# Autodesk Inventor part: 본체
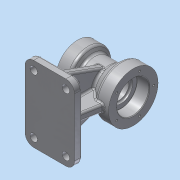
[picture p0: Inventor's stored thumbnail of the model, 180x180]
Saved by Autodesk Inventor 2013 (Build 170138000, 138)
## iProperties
Created: 2015-08
Part Number: 본체
Material: 알루미늄 6061
Document SubType Name: Modeling
Designer: WINDOWS7
Density: 2.71 g/cm^3
Mass: 1062.55 g
Surface Area: 748.24 cm^2
Volume: 392.085 cm^3
Author: WINDOWS7
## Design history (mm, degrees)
sketch "스케치1"
  geometry: L1 (-45, 0)-(45, 0); L2 (-45, 0)-(-45, 35); L3 (-45, 35)-(-25, 35); L4 (-25, 35)-(-19.804, 26); L5 (-19.804, 26)-(8.315, 26); L6 (8.315, 26)-(25, 40); L7 (25, 40)-(45, 40); L8 (45, 40)-(45, 0); 2 further points
  constraints: 16 end point, 3 parallel, 2 perpendicular, 1 coincident, 1 horizontal, 1 midpoint
  dimensions: "d0" = 90 distance of L1.start L1.end; "d2" = 80 diameter of L7 L1; "d3" = 70 diameter of L3 L1; "d4" = 20 distance of L2.end L3.end; "d5" = 20 distance of L6.end L7.end; "d6" = 60 deg angle of L5 L4; "d7" = 40 deg angle of L5 L6; "d8" = 52 diameter of L5 L1
revolve "회전1" sketch "스케치1" stored, may be unused: angle "d9" = 90 deg
node "작업 평면1"
sketch "스케치2"
  geometry: L1 (-40, 61)-(40, 61); L2 (40, 61)-(40, -61); L3 (40, -61)-(-40, -61); L4 (-40, -61)-(-40, 61); 3 further points
  constraints: 8 end point, 2 midpoint, 2 parallel, 1 horizontal, 1 horizontal alignment, 1 perpendicular, 1 vertical alignment
  dimensions: "d11" = 80 distance of L1.start L1.end; "d13" = 122 distance of L1.end L2.end
extrude "돌출1" join sketch "스케치2" distance "d14" = 12; taper "d15" = 0 deg
node "작업 평면2"
sketch "스케치3"
  geometry: L1 (-40, -90)-(40, -90) reference; L2 (-40, -90)-(-40, -78) reference; L3 (40, -78)-(-40, -78) reference; L4 (40, -90)-(40, -78) reference; L5 (30, -78)-(41.917, -10.416); L6 (41.917, -10.416)-(-30, -10.416); L7 (-30, -10.416)-(-30, -78); 1 further point
  constraints: 6 end point, 2 perpendicular, 2 point on line
  dimensions: "d17" = 10 distance of L3.start L5.start; "d18" = 80 deg angle of L3 L5; "d19" = 10 distance from line of L7 L2.end; "d20" = 71.91687 distance of L5.end L6.end
extrude "돌출2" join sketch "스케치3" stored distance "d21" = 12; taper "d22" = 0 deg
sketch "스케치4"
  geometry: L1 (-90, 61)-(-90, -61) reference; L2 (-90, 61)-(-78, 61) reference; L3 (-78, -61)-(-78, 61) reference; L4 (-90, -61)-(-78, -61) reference; L5 (-78, -51)-(7.172, -20); L6 (7.172, -20)-(7.172, 20); L7 (7.172, 20)-(-78, 51); 1 further point
  constraints: 6 end point, 2 point on line, 1 equal length, 1 perpendicular
  dimensions: "d23" = 10 distance of L3.start L5.start; "d24" = 70 deg angle of L3 L5; "d25" = 10 distance of L2.end L7.end; "d26" = 40 distance of L5.end L6.end
extrude "돌출3" join sketch "스케치4" stored distance "d27" = 12; taper "d28" = 0 deg
sketch "스케치5"
  geometry: L1 (40, 61)-(-40, 61) reference; L2 (40, -61)-(40, 61) reference; C1 r 6 at (26, 47); C2 r 6 at (26, -47); C3 r 6 at (-26, -47); C4 r 6 at (-26, 47); 1 further point
  constraints: 4 centre point, 3 equal radius, 2 horizontal alignment, 2 vertical alignment
  dimensions: "d29" = 12 diameter of C1; "d31" = 14 distance from line of L1 C1.centre; "d32" = 94 distance of C2.centre C1.centre; "d33" = 14 distance from line of L2 C2.centre; "d34" = 52 distance of C3.centre C2.centre
extrude "돌출4" cut sketch "스케치5" stored distance "d35" = 12; taper "d36" = 0 deg
sketch "스케치6"
  geometry: L1 (-90, 61)-(-90, -61) reference; L2 (-78, -61)-(-78, 61) reference; L3 (-54, 30)-(-60, 30); L4 (-54, 18)-(-60, 18); L5 (-54, -18)-(-60, -18); L6 (-54, -30)-(-60, -30); A1 r 6 centre (-60, 24) between (-60, 30) and (-60, 18); A2 r 6 centre (-54, 24) between (-54, 18) and (-54, 30); A3 r 6 centre (-60, -24) between (-60, -18) and (-60, -30); A4 r 6 centre (-54, -24) between (-54, -30) and (-54, -18); 3 further points
  constraints: 8 end point, 8 point on circle, 4 centre point, 4 tangent, 3 equal radius, 3 parallel, 2 horizontal alignment, 1 coincident, 1 midpoint, 1 perpendicular
  dimensions: "d41" = 24 vertical distance of point (-90, 0) point (-60, 24); "d42" = 12 diameter of A1; "d43" = 18 distance from line of A1.centre L2; "d44" = 18 dimension on A1 A2; "d45" = 18 dimension on A3 A4; "d46" = 18 distance from line of L2 A3.centre; "d47" = 48 distance of A3.centre point (-60, 24)
extrude "돌출5" cut sketch "스케치6" stored distance "d48" = 12; taper "d49" = 0 deg
fillet "모깎기1" dims "d50" = 14
sketch "스케치7"
  geometry: C1 r 40 at (0, 0) reference; C2 r 26 at (0, 0)
  constraints: 1 centre point, 1 coincident
  dimensions: "d51" = 52 diameter of C2
extrude "돌출6" cut sketch "스케치7" distance "d53" = 20; taper "d54" = 0 deg
sketch "스케치8"
  geometry: C1 r 26 at (0, 0) reference; C2 r 19 at (0, 0)
  constraints: 1 centre point, 1 coincident
  dimensions: "d55" = 38 diameter of C2
extrude "돌출7" cut sketch "스케치8" distance "d57" = 3; taper "d58" = 0 deg
sketch "스케치9"
  geometry: C1 r 35 at (0, 0) reference; C2 r 20 at (0, 0)
  constraints: 1 centre point, 1 coincident
  dimensions: "d59" = 40 diameter of C2
extrude "돌출8" cut sketch "스케치9" distance "d61" = 17; taper "d62" = 0 deg
sketch "스케치10"
  geometry: C1 r 20 at (0, 0) reference; C2 r 16 at (0, 0)
  constraints: 1 centre point, 1 coincident
  dimensions: "d63" = 32 diameter of C2
extrude "돌출9" cut sketch "스케치10" stored distance "d65" = 17; taper "d66" = 0 deg
chamfer "모따기1" distance "d67" = 1; stored, may be unused: second distance "d68" = 2, angle "d69" = 45 deg
fillet "모깎기2" dims "d70" = 3
fillet "모깎기3" dims "d71" = 3
fillet "모깎기4" dims "d72" = 0.3
fillet "모깎기5" dims "d73" = 5
sketch "스케치11" dims "d74" = 54
  geometry: C1 r 35 at (0, 0) reference; C2 r 21 at (0, 0) reference; 6 further points
  constraints: 2 vertical alignment, 1 coincident, 8 other
  dimensions: "d78" = 360 deg dimension on C1.centre point (0, 27) (derived)
hole "구멍1" sketch "스케치11" at (0, 27), (-25.679, 8.343), (-15.87, -21.843), (15.87, -21.843), (25.679, 8.343) diameter "d80" = 3.242; stored, may be unused: countersink angle "d84" = 90 deg, drill point angle "d86" = 118 deg; dims "d81" = 10, "d82" = 4, "d83" = 2, "d85" = 13
sketch "스케치12" dims "d87" = 66
  geometry: C1 r 40 at (0, 0) reference; C2 r 27 at (0, 0) reference; 6 further points
  constraints: 2 vertical alignment, 1 coincident, 8 other
  dimensions: "d91" = 360 deg dimension on C1.centre point (0, 33) (derived)
hole "구멍2" sketch "스케치12" at (0, 33), (-31.385, 10.198), (-19.397, -26.698), (19.397, -26.698), (31.385, 10.198) diameter "d93" = 3.242; stored, may be unused: countersink angle "d97" = 90 deg, drill point angle "d99" = 118 deg; dims "d94" = 10, "d95" = 4, "d96" = 2, "d98" = 13
fillet "모깎기6" dims "d100" = 3
fillet "모깎기7" dims "d101" = 3
sketch "스케치13"
  geometry: L1 (-30, -37.881)-(-30, -75) reference; L2 (26, -78)-(-26, -78) reference; 2 further points
  constraints: 1 other
  dimensions: "d102" = 24 distance from line of point (-14, -54) L2; "d103" = 16 distance from line of point (-14, -54) L1
feature "엠보싱1" sketch "스케치13" dims "d0" = 90, "d2" = 80, "d3" = 70, "d4" = 20, "d5" = 20, "d6" = 60 deg, "d7" = 40 deg, "d8" = 52, "d104" = 0.5, "d105" = 0
node "솔리드1"
node "투영된 루프1"
node "투영된 루프2"
other parameters: "d16" = 0
